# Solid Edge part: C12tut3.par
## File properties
Author: Ashutosh-CADCIM
Template: ansi inch part.par
Last saved by: SOFT
Revision: 4
Application: Solid Edge
Accuracy: 0.990
Username: Ashutosh-CADCIM
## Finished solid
Body 1: solid body, 12 faces, 16 edges, 6 vertices.
  Faces by surface: plane 8, cylinder 4
  Edges by curve: circle 8, line 7, ellipse 1
Bounding box of the edges (mm): 31.750 x 82.478 x 31.750, from (-15.875, -77.9793, -15.875) to (15.875, 4.4987, 15.875).
Cylindrical faces by radius (mm): R5.5944 x1, R6.35 x1, R7.9375 x1, R15.875 x1
Planar faces by outward normal: +x 1, +y 1, -x 1, -y 4, oblique 1
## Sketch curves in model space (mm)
line (-22.318, -0.2404, 12.6982) -> (-22.2829, -4.9679, 7.9011)
line (-22.2618, -77.9738, 5.0232) -> (-22.2673, -0.1897, 5.7686)
line (-22.1798, -77.8918, -6.1649) -> (-22.1842, -0.1066, -5.5759)
line (-22.2202, -89.5716, -0.6561) -> (-22.2258, 15.4021, 0.1128)
line (-22.2678, -68.4546, 5.8486) -> (-22.2673, -77.9793, 5.7788)
line (-22.2673, -77.9793, 5.7788) -> (-22.1743, -77.8863, -6.9205)
line (-22.1748, -68.3616, -6.8507) -> (-22.1743, -77.8863, -6.9205)
line (-22.3413, -0.2637, 15.8731) -> (-22.1087, -0.0311, -15.8752)
line (-22.3415, 4.4987, 15.908) -> (-22.3413, -0.2637, 15.8731)
line (-22.3415, 4.4987, 15.908) -> (-22.109, 4.7312, -15.8403)
line (-22.109, 4.7312, -15.8403) -> (-22.1087, -0.0311, -15.8752)
line (-22.1669, -0.0893, -7.9382) -> (-22.1632, -68.3499, -8.4381)
line (-22.2831, -0.2055, 7.936) -> (-22.2795, -68.4662, 7.436)
line (-22.2795, -68.4662, 7.436) -> (-22.1632, -68.3499, -8.4381)
line (0, 0, 22.225) -> (0, 0, -22.225)
line (22.225, 0, 0) -> (-22.225, 0, 0)
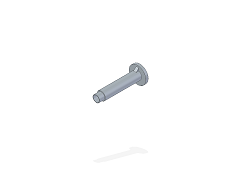
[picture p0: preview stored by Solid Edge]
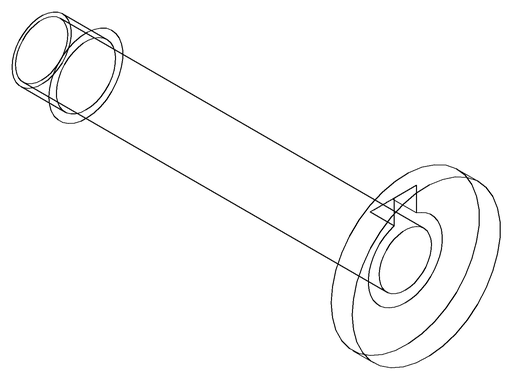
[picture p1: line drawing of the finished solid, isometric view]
